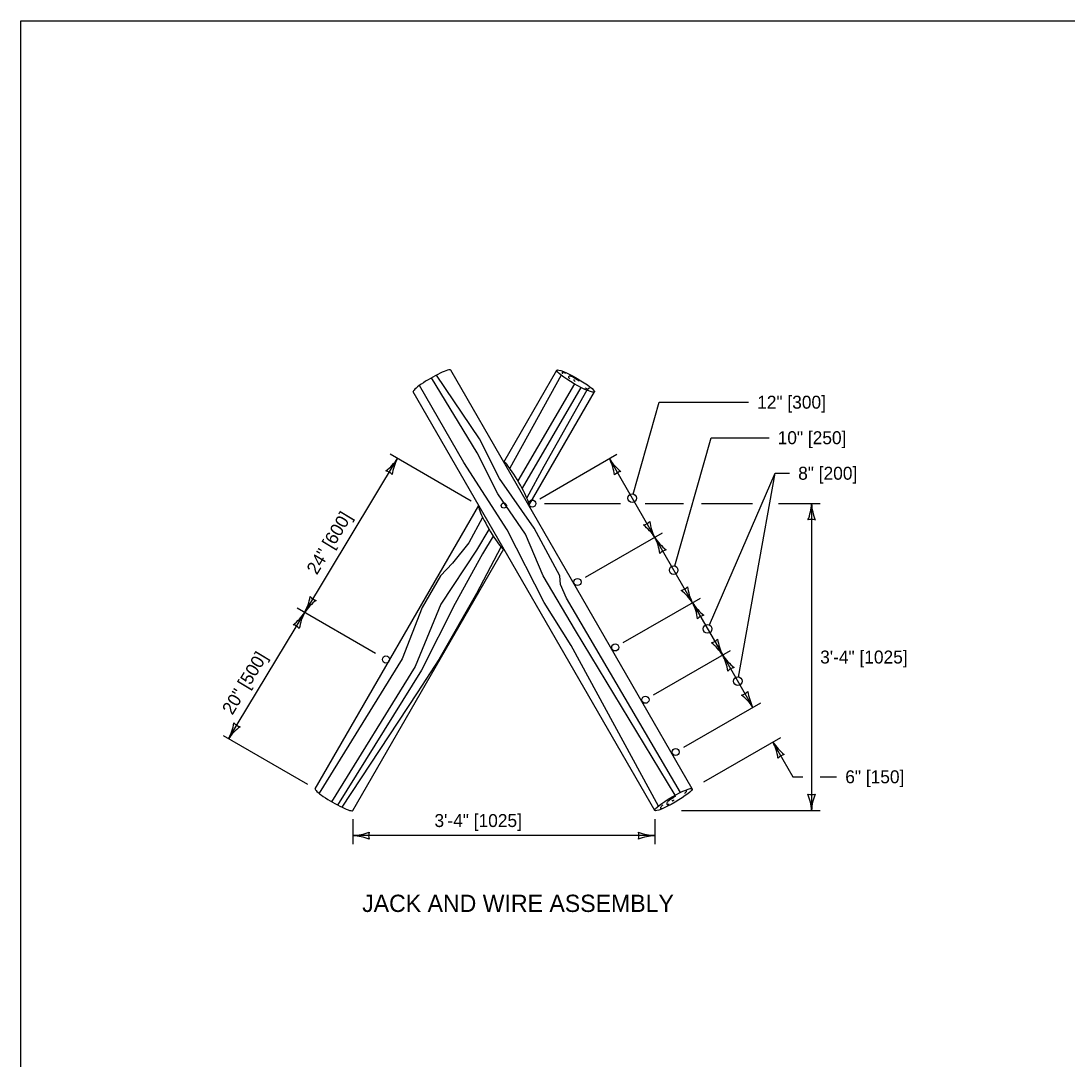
# Model space of a CAD drawing. Extents: x 49991.4 to 50021, y 49987.6 to 50011.4.
# Drawn here: x 49999.384 to 50004.231, y 49994.19 to 49998.999 of the extents above; entities that cross this region are included whole.
import ezdxf

# ---------------------------------------------------------------- set-up
doc = ezdxf.new("R2010")
doc.units = 0
for name, color, linetype in [('Level 1', 7, 'Continuous'), ('Level 2', 7, 'Continuous'), ('Level 3', 7, 'Continuous')]:
    doc.layers.add(name, color=color, linetype=linetype)

msp = doc.modelspace()

# ---------------------------------------------------------------- linework, layer by layer
at = {"layer": 'Level 1'}
for p, q in [((50002.4946, 49995.4423), (50001.3749, 49997.3816)), ((50001.6211, 49996.9553), (50001.8668, 49997.381)), ((50002.3207, 49995.3412), (50001.201, 49997.2806)), ((50001.737, 49996.7542), (50002.041, 49997.2803)), ((50000.7472, 49995.4416), (50001.5049, 49996.7541)), ((50000.9215, 49995.3412), (50001.621, 49996.553))]:
    msp.add_line(p, q, dxfattribs=at)
msp.add_lwpolyline([(49999.3835, 49998.9992), (50016.7501, 49998.9992), (50016.7501, 49987.7988), (49999.3835, 49987.7988)], close=True, dxfattribs=at)
for points in [[(50002.4147, 49995.412), (50001.9536, 49996.1745), (50001.8038, 49996.4281), (50001.7216, 49996.6221), (50001.5938, 49996.8082), (50001.497, 49996.9981), (50001.2868, 49997.3463)], [(50002.4403, 49995.4253), (50001.9118, 49996.3251), (50001.8833, 49996.3888), (50001.881, 49996.4279), (50001.7618, 49996.6496), (50001.6015, 49996.879), (50001.5082, 49997.0627), (50001.3096, 49997.3587)], [(50001.8865, 49997.3582), (50001.649, 49996.9269)], [(50002.3373, 49995.3616), (50001.9332, 49996.105), (50001.8079, 49996.3053), (50001.6373, 49996.6409), (50001.4353, 49996.9541), (50001.2304, 49997.3103)], [(50001.9488, 49997.3173), (50001.6868, 49996.8683)], [(50001.9777, 49997.3016), (50001.7057, 49996.8347)], [(50002.0065, 49997.2881), (50001.8063, 49996.9354), (50001.7278, 49996.7897)], [(50001.523, 49996.698), (50001.4584, 49996.5808), (50001.3838, 49996.4874), (50001.3277, 49996.4287), (50001.2433, 49996.2811), (50001.1503, 49996.0431), (50000.7648, 49995.421)], [(50001.5524, 49996.6434), (50001.4944, 49996.5469), (50001.3298, 49996.2969), (50001.2111, 49996.0086), (50000.8229, 49995.382)], [(50001.5718, 49996.6115), (50001.5231, 49996.5308), (50001.3955, 49996.3003), (50001.2395, 49995.992), (50000.8511, 49995.3663)], [(50001.6069, 49996.5619), (50001.4942, 49996.3465), (50001.3193, 49996.04), (50001.2197, 49995.8871), (50000.8702, 49995.3566)]]:
    msp.add_lwpolyline(points, dxfattribs=at)
for centre, radius in [((50001.621, 49996.7541), 0.012), ((50001.7528, 49996.7632), 0.0165), ((50001.9627, 49996.3996), 0.0165), ((50002.1376, 49996.0967), 0.0165), ((50001.0751, 49996.0408), 0.0165), ((50002.2775, 49995.8544), 0.0165), ((50002.4174, 49995.612), 0.0165)]:
    msp.add_circle(centre, radius, dxfattribs=at)
for centre, major_axis, ratio, start_param, end_param in [((50001.2881, 49997.3308), (-0.0869, -0.0505), 0.139914, 3.139201, 6.283242), ((50001.6791, 49996.8547), (-0.058, 0.1005), 0.116358, 3.14115, 6.28555), ((50001.5629, 49996.6535), (-0.058, 0.1006), 0.116361, 0.000894, 3.157998), ((50000.8344, 49995.3916), (-0.0871, 0.0503), 0.139914, 6.282865, 9.424578)]:
    msp.add_ellipse(centre, major_axis=major_axis, ratio=ratio, start_param=start_param, end_param=end_param, dxfattribs=at)
for centre, major_axis in [((50001.9539, 49997.3306), (-0.0871, 0.0503)), ((50002.4076, 49995.3918), (-0.0869, -0.0505))]:
    msp.add_ellipse(centre, major_axis=major_axis, ratio=0.139914, dxfattribs=at)
for points in [[(50001.9091, 49997.3665), (50001.9028, 49997.3696), (50001.8958, 49997.3716), (50001.8923, 49997.3703), (50001.8917, 49997.3689), (50001.893, 49997.3652), (50001.8935, 49997.364)], [(50001.97, 49997.3301), (50001.9634, 49997.3353), (50001.9532, 49997.3413), (50001.9435, 49997.3473), (50001.9337, 49997.3522), (50001.9282, 49997.3536), (50001.9235, 49997.353), (50001.9214, 49997.3509), (50001.9208, 49997.3481), (50001.9222, 49997.3458), (50001.9258, 49997.3417)], [(50001.9477, 49997.3358), (50001.9461, 49997.3362), (50001.9458, 49997.3353), (50001.9478, 49997.3328), (50001.9489, 49997.3319), (50001.951, 49997.3299), (50001.9521, 49997.3302)], [(50002.0133, 49997.2991), (50002.0151, 49997.2971), (50002.015, 49997.2949), (50002.0126, 49997.2936), (50002.0065, 49997.2945), (50001.9989, 49997.2974)], [(50002.4162, 49995.4063), (50002.4087, 49995.4024), (50002.399, 49995.3956), (50002.3895, 49995.3892), (50002.381, 49995.3823), (50002.3775, 49995.378), (50002.3761, 49995.3734), (50002.3772, 49995.3706), (50002.3795, 49995.3689), (50002.3821, 49995.3692), (50002.3873, 49995.3709)], [(50002.4621, 49995.433), (50002.4647, 49995.4338), (50002.4666, 49995.4327), (50002.4669, 49995.43), (50002.4635, 49995.4247), (50002.4578, 49995.419)], [(50002.3578, 49995.3659), (50002.3524, 49995.3614), (50002.3477, 49995.3558), (50002.3474, 49995.3521), (50002.3485, 49995.351), (50002.3524, 49995.3507), (50002.3537, 49995.3506)], [(50002.4018, 49995.3883), (50002.4007, 49995.3871), (50002.4014, 49995.3863), (50002.4044, 49995.3871), (50002.4057, 49995.3878), (50002.4084, 49995.389), (50002.4087, 49995.39)]]:
    msp.add_spline(points, degree=3, dxfattribs=at)
at = {"layer": 'Level 3'}
for p, q in [((50000.6984, 49996.2583), (50001.1285, 49996.9714)), ((50001.4703, 49996.7741), (50001.0938, 49996.9914)), ((50002.1455, 49996.9899), (50001.7885, 49996.7837)), ((50002.1109, 49996.9699), (50002.3208, 49996.6064)), ((50002.7091, 49995.9596), (50002.878, 49996.9037)), ((50001.8093, 49996.7632), (50002.1613, 49996.7632)), ((50002.2764, 49996.7632), (50002.4538, 49996.7632)), ((50002.5369, 49996.7632), (50002.7736, 49996.7632)), ((50002.8935, 49996.7632), (50003.0872, 49996.7632)), ((50003.0472, 49996.7632), (50003.0472, 49995.3412)), ((50002.3554, 49996.6264), (50001.9983, 49996.4202)), ((50002.3208, 49996.6064), (50002.4957, 49996.3034)), ((50002.5303, 49996.3234), (50002.1732, 49996.1173)), ((50001.0262, 49996.0691), (50000.6637, 49996.2783)), ((50002.4957, 49996.3034), (50002.6356, 49996.0611)), ((50000.3454, 49995.673), (50000.6984, 49996.2583)), ((50002.6702, 49996.0811), (50002.3132, 49995.8749)), ((50002.6356, 49996.0611), (50002.7755, 49995.8187)), ((50002.8101, 49995.8387), (50002.4531, 49995.6326)), ((50000.7125, 49995.4616), (50000.3223, 49995.6869)), ((50002.9029, 49995.6781), (50002.5458, 49995.4719)), ((50002.8683, 49995.6581), (50002.961, 49995.4974)), ((50002.8683, 49995.6581), (50002.961, 49995.4974)), ((50000.9215, 49995.3012), (50000.9215, 49995.1846)), ((50002.3207, 49995.3012), (50002.3207, 49995.1846)), ((50002.4441, 49995.3412), (50003.0872, 49995.3412)), ((50002.3207, 49995.2246), (50000.9215, 49995.2246))]:
    msp.add_line(p, q, dxfattribs=at)
for points in [[(50002.2213, 49996.8074), (50002.3415, 49997.2328), (50002.7552, 49997.2328)], [(50002.4137, 49996.4741), (50002.5816, 49997.0683), (50002.8502, 49997.0683)], [(50002.5736, 49996.2006), (50002.878, 49996.9037), (50002.9452, 49996.9037)], [(50002.8683, 49995.6581), (50002.961, 49995.4974), (50003.0072, 49995.4974)], [(50003.0872, 49995.4974), (50003.1634, 49995.4974)]]:
    msp.add_lwpolyline(points, dxfattribs=at)
for centre in [(50002.2158, 49996.7881), (50002.4082, 49996.4549), (50002.5656, 49996.1823), (50002.7055, 49995.9399)]:
    msp.add_circle(centre, 0.02, dxfattribs=at)
for centre, radius, start, end in [((50000.943, 49997.094), 0.2223, 306.3606, 326.5441), ((50001.3337, 49996.8611), 0.233, 151.7319, 170.9818), ((50001.9139, 49996.8667), 0.2223, 7.456, 27.6395), ((50002.3067, 49997.0962), 0.233, 212.8273, 232.0772), ((50001.0623, 49996.8616), 0.0548, 41.0434, 76.7658), ((50002.175, 49996.8588), 0.0548, 102.1388, 137.8612), ((50002.825, 49996.7723), 0.2223, 337.456, 357.6395), ((50003.2799, 49996.7746), 0.233, 182.8273, 202.0772), ((50002.2567, 49996.7174), 0.0548, 282.1388, 317.8612), ((50002.125, 49996.4801), 0.233, 32.8273, 52.0772), ((50002.5177, 49996.7095), 0.2223, 187.456, 207.6395), ((50003.0472, 49996.6349), 0.0548, 72.1388, 107.8612), ((50002.1238, 49996.5032), 0.2223, 7.456, 27.6395), ((50002.5166, 49996.7327), 0.233, 212.8273, 232.0772), ((50002.3849, 49996.4953), 0.0548, 102.1388, 137.8612), ((50002.4316, 49996.4145), 0.0548, 282.1388, 317.8612), ((50002.6926, 49996.4066), 0.2223, 187.456, 207.6395), ((50000.4932, 49996.3687), 0.233, 331.7319, 350.9818), ((50000.8839, 49996.1358), 0.2223, 126.3606, 146.5441), ((50000.7646, 49996.3681), 0.0548, 221.0434, 256.7658), ((50002.2999, 49996.1771), 0.233, 32.8273, 52.0772), ((50002.2987, 49996.2003), 0.2223, 7.456, 27.6395), ((50002.6915, 49996.4297), 0.233, 212.8273, 232.0772), ((50000.5129, 49996.3809), 0.2223, 306.3606, 326.5441), ((50000.9036, 49996.148), 0.233, 151.7319, 170.9818), ((50002.5598, 49996.1924), 0.0548, 102.1388, 137.8612), ((50000.6322, 49996.1485), 0.0548, 41.0434, 76.7658), ((50002.5715, 49996.1721), 0.0548, 282.1388, 317.8612), ((50002.8325, 49996.1642), 0.2223, 187.456, 207.6395), ((50002.4398, 49995.9348), 0.233, 32.8273, 52.0772), ((50002.4386, 49995.958), 0.2223, 7.456, 27.6395), ((50002.8314, 49996.1874), 0.233, 212.8273, 232.0772), ((50002.6997, 49995.9501), 0.0548, 102.1388, 137.8612), ((50002.7114, 49995.9298), 0.0548, 282.1388, 317.8612), ((50002.9725, 49995.9219), 0.2223, 187.456, 207.6395), ((50002.5797, 49995.6924), 0.233, 32.8273, 52.0772), ((50000.1401, 49995.7833), 0.233, 331.7319, 350.9818), ((50000.4116, 49995.7827), 0.0548, 221.0434, 256.7658), ((50000.5308, 49995.5504), 0.2223, 126.3606, 146.5441), ((50002.6713, 49995.5549), 0.2223, 7.456, 27.6395), ((50003.064, 49995.7844), 0.233, 212.8273, 232.0772), ((50002.9324, 49995.547), 0.0548, 102.1388, 137.8612), ((50003.0472, 49995.4694), 0.0548, 252.1388, 287.8612), ((50002.8144, 49995.3297), 0.233, 2.8273, 22.0772), ((50003.2693, 49995.3321), 0.2223, 157.456, 177.6395), ((50000.91, 49995.4573), 0.233, 272.8273, 292.0772), ((50000.9123, 49995.0025), 0.2223, 67.456, 87.6395), ((50001.0497, 49995.2246), 0.0548, 162.1388, 197.8612), ((50002.3298, 49995.4467), 0.2223, 247.456, 267.6395), ((50002.1924, 49995.2246), 0.0548, 342.1388, 17.8612), ((50002.3321, 49994.9919), 0.233, 92.8273, 112.0772)]:
    msp.add_arc(centre, radius, start, end, dxfattribs=at)

# ---------------------------------------------------------------- texts
at = {"layer": 'Level 2'}
for s, height, p in [('12" [300]', 0.06, (50002.7952, 49997.2028)), ('10" [250]', 0.06, (50002.8902, 49997.0383)), ('8" [200]', 0.06, (50002.9852, 49996.8737)), ('3\'-4" [1025]', 0.06, (50003.0872, 49996.0222)), ('3\'-4" [1025]', 0.06, (50001.2998, 49995.2646)), ('JACK AND WIRE ASSEMBLY', 0.08, (50000.9647, 49994.8711))]:
    msp.add_text(s, height=height, dxfattribs=at).set_placement(p)
for s, rotation, p in [('24" [600]', 58.9046, (50000.7549, 49996.4294)), ('20" [500]', 58.9046, (50000.3633, 49995.7802)), ('6" [150]', 360, (50003.2034, 49995.4674))]:
    msp.add_text(s, height=0.06, rotation=rotation, dxfattribs=at).set_placement(p)

doc.saveas('drawing.dxf')
